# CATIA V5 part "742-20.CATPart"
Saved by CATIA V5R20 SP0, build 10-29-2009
Part number: 742-20
Bounding box of the stored display mesh (mm): x -20 to 21.5, y -20 to 20, z -23 to 36
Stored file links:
  C:\Users\Utente\Desktop\IO LAVORO\3D X SITO CF\X SITO\742\742-20.CATPart
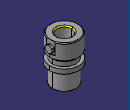
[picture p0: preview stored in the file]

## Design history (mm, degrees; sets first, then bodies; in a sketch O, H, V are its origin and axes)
Set1
  DatumSurface1 to DatumSurface38 "742-20"
Body1 (main body)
